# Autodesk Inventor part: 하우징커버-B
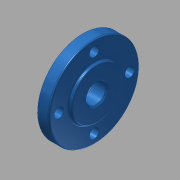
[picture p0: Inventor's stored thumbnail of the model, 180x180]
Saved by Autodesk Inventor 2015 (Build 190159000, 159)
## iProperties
Created: 2018-01
Part Number: 하우징커버-B
Material: 알루미늄 6061
Document SubType Name: Modeling
Designer: mduedu
Density: 2.71 g/cm^3
Appearance: 청록색
Mass: 8.4704 g
Surface Area: 21.4635 cm^2
Volume: 3.12561 cm^3
Author: mduedu
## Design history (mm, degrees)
sketch "스케치1"
  geometry: C1 r 16 at (0, 0); 1 further point
  constraints: 1 centre point, 1 coincident
  dimensions: "d0" = 32 diameter of C1
extrude "돌출1" new body sketch "스케치1" distance "d1" = 4; taper "d2" = 0 deg
sketch "스케치2"
  geometry: C1 r 9 at (0, 0); 1 further point
  constraints: 1 centre point, 1 coincident
  dimensions: "d3" = 18 diameter of C1
extrude "돌출2" join sketch "스케치2" distance "d4" = 1; taper "d5" = 0 deg
fillet "모깎기1" dims "d6" = 0.5
fillet "모깎기2" dims "d7" = 0.5
hole "구멍1" diameter "d10" = 7; stored, may be unused: countersink angle "d14" = 90 deg, drill point angle "d16" = 118 deg; dims "d8" = 10, "d9" = 10, "d11" = 6, "d12" = 4, "d13" = 2, "d15" = 8
chamfer "모따기1" distance "d17" = 0.5; stored, may be unused: second distance "d18" = 2, angle "d19" = 45 deg
sketch "스케치3" dims "d21" = 25
  geometry: 6 further points
  constraints: 2 vertical alignment, 1 coincident, 7 other
  dimensions: "d24" = 360 deg dimension on point (0, 0) point (0, 12.5) (derived)
sketch "스케치4"
  geometry: 4 further points
  constraints: 4 other
hole "구멍2" sketch "스케치4" at (-12.5, 0), (0, -12.5), (12.5, 0), (0, 12.5) diameter "d26" = 3.4; stored, may be unused: countersink angle "d30" = 90 deg, drill point angle "d32" = 0 deg; dims "d27" = 6, "d28" = 4, "d29" = 2, "d31" = 8
node "솔리드1"
